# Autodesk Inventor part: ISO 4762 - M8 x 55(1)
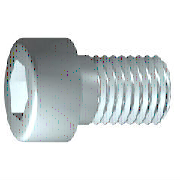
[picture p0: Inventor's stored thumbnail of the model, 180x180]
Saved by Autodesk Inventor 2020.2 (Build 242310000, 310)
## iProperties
Created: 2019-01
Part Number: ISO 4762 - M8 x 55(1)
Material: Edelstahl, 440C
Description: Innensechskantschraube
Document SubType Name: Modeling
Standard: ISO 4762
Designer: lutzd
Standard Revision: Fourth edition 2004-03-01
Standards Organization: ISO
Language: de-DE
Size Designation: M8 x 55
Categories: <MemberInstance><Categories><Category DisplayName="Verbindungselemente" InternalName="e4da775c-781d-43d5-af7c-5136215cf5a6" Mnemonic="FSTN"><Category DisplayNam
Mass: 28.4037 g
Surface Area: 20.3867 cm^2
Volume: 3.66499 cm^3
Density: 7.75 g/cm^3
Appearance: Semi-Polished(3)
IsCustomPart: 0
Author: lutzd
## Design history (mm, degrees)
body "Solid1"
sketch "Skizze1"
  geometry: L1 (-2, 0)-(55, 0); L2 (55, 0)-(55, 4); L3 (55, 4)-(27, 4); L4 (27, 4)-(26.233, 4); L5 (26.233, 4)-(0, 4); L6 (0, 4)-(0, 6.5); L7 (0, 6.5)-(-8, 6.5); L8 (-8, 6.5)-(-8, 3.464); L9 (-8, 3.464)-(-4, 3.464); L10 (-4, 3.464)-(-2, 0); L11 (-20.6, 0)-(67.6, 0) reference; L12 (0, -1.3)-(0, 7.8) reference; L13 (27, 4)-(0, 4)
  constraints: 22 end point, 6 parallel, 2 collinear, 2 perpendicular, 1 horizontal, 1 point on line
  dimensions: "d1" = 28 distance from line of L3.end L2 (= GEL); "d2" = 0.76691 distance of L4.end L3.end (computed from GAL); "d3" = 8 distance between parallel lines of L8 L6 (= KOH); "d4" = 4 distance of L8.end L9.end (= INTI); "d5" = 60 deg angle of L10 L1; "d6" = 8 diameter of L3 L1 (= GD); "d7" = 8 diameter of L5 L1 (= BDM); "d8" = 6.9282 diameter of L9 L1 (= 1.1547 x SW); "d9" = 13 diameter of L7 L1 (= KOD); "d26" = 55 distance between parallel lines of L12 L2 (= NLG)
workplane "Work Plane1"
fillet "Fillet2" dims "d30" = 0.1 (= R)
revolve "Körper" stored, may be unused: angle "d10" = 90 deg
sketch "Skizze2"
  geometry: L1 (0, -9.1)-(0, 9.1) reference; L2 (-9.1, 0)-(9.1, 0) reference; L3 (3.464, 0)-(1.732, -3); L4 (1.732, -3)-(-1.732, -3); L5 (-1.732, -3)-(-3.464, 0); L6 (-3.464, 0)-(-1.732, 3); L7 (-1.732, 3)-(1.732, 3); L8 (1.732, 3)-(3.464, 0); 2 further points
  constraints: 12 end point, 1 coincident, 1 horizontal alignment, 1 point on line, 12 other
extrude "Loch" join sketch "Skizze2" stored distance "d11" = 10; taper "d12" = 0 deg
fillet "Rundung1" dims "d17" = 0.8 (= RR)
feature "Gewinde" dims "d13" = 28 (= GEL), "d14" = 0
chamfer "Fase1" distance "d15" = 0.76681 (= -0.5 x SPD + 0.5 x GD); stored, may be unused: second distance "d16" = 0.76681 (= GUL), angle "d27" = 45 deg
other parameters: "GD" = 8 [user parameter; used in 2 equation terms], "NLG" = 55 [user parameter; used in 1 equation term], "GEL" = 28 [user parameter; used in 2 equation terms], "KOD" = 13 [user parameter; used in 1 equation term], "KOH" = 8 [user parameter; used in 1 equation term], "INTI" = 4 [user parameter; used in 1 equation term], "GAL" = 0.76681 (= 0.61345 x PTC) [user parameter; used in 1 equation term], "GUL" = 0.76681 (= 0.61345 x PTC) [user parameter; used in 1 equation term], "BDM" = 8 (= NND) [user parameter; used in 1 equation term], "SW" = 6 [user parameter; used in 2 equation terms], "RR" = 0.8 [user parameter; used in 1 equation term], "SPD" = 6.46637 (= NND - 1.2269 x PTC) [user parameter; used in 1 equation term], "d19" = 0, "d28" = 0, "d29" = 0, "R" = 0.1 [user parameter; used in 1 equation term], "TOA" = 30 deg [user parameter], "GD1" = 6.46637 (= THREADDIA - 1.2269 x PTC) [user parameter], "THREADDIA" = 8 [user parameter; used in 1 equation term], "FAWI" = 45 deg [user parameter], "TPU" = 8 (computed from PTC) [user parameter], "PTC" = 1.25 [user parameter; used in 5 equation terms], "NND" = 8 [user parameter; used in 2 equation terms], "E0" = 6.93 (= 1.155 x SW) [user parameter]
